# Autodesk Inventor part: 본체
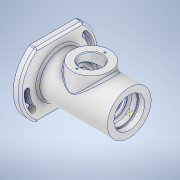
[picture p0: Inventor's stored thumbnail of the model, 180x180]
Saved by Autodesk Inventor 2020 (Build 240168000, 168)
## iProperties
Created: 2022-05
Part Number: 본체
Material: 알루미늄 6061
Document SubType Name: Modeling
Designer: Student
Density: 2.7 g/cm^3
Appearance: 알루미늄 - 평지
Mass: 703.309 g
Surface Area: 623.432 cm^2
Volume: 260.485 cm^3
Author: Student
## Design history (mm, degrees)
sketch "스케치1"
  geometry: L1 (65.838, 0)-(-65.838, 0); L2 (56, 32)-(-46, 32); L3 (-23.801, 32)-(-46, 32); L4 (-46, 32)-(-46, 58); L5 (-46, 58)-(-56, 58); L6 (-56, 58)-(-56, 36); L7 (-56, 36)-(-59, 36); L8 (-59, 36)-(-59, 30); L9 (-59, 30)-(-45, 20); L10 (-45, 20)-(-45, 15.19); L11 (-37.7, 14.786)-(-37.7, 11); L12 (-37.7, 11)-(-35, 11); L13 (-35, 11)-(-35, 15); L14 (-35, 15)-(-30, 15); L15 (-30, 15)-(-30, 17.5); L16 (-30, 17.5)-(-19, 17.5); L17 (-19, 17.5)-(-19, 27); L18 (-19, 27)-(19, 27); L19 (19, 27)-(19, 17.5); L20 (34, 17.5)-(34, 22.5); L21 (34, 22.5)-(45, 22.5); L22 (45, 22.5)-(45, 24); L23 (45, 24)-(48, 24); L24 (48, 24)-(48, 22.5); L25 (48, 22.5)-(56, 22.5); L26 (56, 22.5)-(56, 32); L27 (34, 17.5)-(30, 17.5); L28 (28.25, 17.5)-(28.25, 18.5); L29 (28.25, 18.5)-(30, 18.5); L30 (30, 18.5)-(30, 17.5); L31 (28.25, 17.5)-(19, 17.5); L32 (-44.3, 14.786)-(-45, 15.19); L33 (-44.3, 14.786)-(-37.7, 14.786); 2 further points
  constraints: 66 end point, 25 perpendicular, 3 horizontal, 1 coincident, 1 horizontal alignment, 1 midpoint, 1 point on line
  dimensions: "d2" = 102 distance between parallel lines of L4 L26; "d3" = 13 distance between parallel lines of L8 L4; "d4" = 3 distance of L6.end L7.end; "d5" = 64 diameter of L2 L1; "d6" = 48 diameter of L23 L1; "d7" = 45 diameter of L21 L1; "d8" = 54 diameter of L18 L1; "d9" = 30 diameter of L14 L1; "d10" = 22 diameter of L12 L1; "d11" = 40 diameter of L9.end L1; "d12" = 60 diameter of L8.end L1; "d13" = 72 diameter of L7 L1; "d14" = 8 distance of L24.end L25.end; "d15" = 3 distance of L22.end L23.end; "d16" = 22 distance between parallel lines of L20 L26; "d17" = 64 distance between parallel lines of L15 L20; "d18" = 11 distance of L27.end L19.end; "d19" = 38 distance of L17.end L18.end; "d20" = 11 distance between parallel lines of L15 L17; "d21" = 60 distance between parallel lines of L15 L30; "d22" = 5 distance between parallel lines of L13 L15; "d23" = 14 distance between parallel lines of L10 L8; "d24" = 116 diameter of L5 L1; "d26" = 37 diameter of L29 L1; "d28" = 1.75 distance of L28.end L29.end; "d29" = 7.3 distance between parallel lines of L10 L11; "d30" = 35 diameter of L31 L1; "d31" = 19 distance from line of point (0, 0) L19; "d32" = 45 diameter of L25 L1; "d33" = 0.7 distance from line of L32.start L10; "d34" = 30 deg angle of L33 L32
revolve "회전1" sketch "스케치1" stored, may be unused: angle "d35" = 90 deg
sketch "스케치2"
  geometry: L1 (-61.819, 47)-(63.766, 47); L2 (-61.819, -47)-(73.988, -47); C1 r 58 at (0, 0) reference; 5 further points
  constraints: 4 end point, 2 horizontal
  dimensions: "d36" = 47 distance from line of point (0, 0) L1; "d37" = 94 distance between parallel lines of L1 L2
extrude "돌출1" cut sketch "스케치2" distance "d38" = 10; taper "d39" = 0 deg
sketch "스케치5"
  geometry: L1 (0, 0)-(75.323, 0); L2 (0, 0)-(56.239, 47.19); C1 r 32 at (0, 0) reference; C2 r 20 at (0, 0) reference; A1 r 48 centre (0, 0) between (36.77, 30.854) and (-48, 0); A2 r 48 centre (0, 0) between (48, 0) and (36.77, 30.854); A3 r 52 centre (0, 0) between (52, 0) and (39.834, 33.425); A4 r 44 centre (0, 0) between (44, 0) and (33.706, 28.283); A5 r 4 centre (48, 0) between (44, 0) and (52, 0); A6 r 4 centre (36.77, 30.854) between (39.834, 33.425) and (33.706, 28.283); A7 r 48 centre (0, 0) between (-48, 0) and (-38.722, -28.366); A8 r 52 centre (0, 0) between (-52, 0) and (-41.949, -30.73); A9 r 44 centre (0, 0) between (-44, 0) and (-35.495, -26.002); A10 r 4 centre (-48, 0) between (-44, 0) and (-52, 0); A11 r 4 centre (-38.722, -28.366) between (-41.949, -30.73) and (-35.495, -26.002); 1 further point
  constraints: 22 point on circle, 11 centre point, 8 tangent, 4 end point, 3 coincident, 2 concentric, 1 horizontal, 1 point on line
  dimensions: "d51" = 96 diameter of A1; "d52" = 40 deg angle of L1 L2; "d53" = 8 diameter of A5; "d54" = 8 diameter of A11 (derived); "d55" = 48.41661 distance from line of L1.end L2; "d56" = 47.18977 distance from line of L2.end L1; "d57" = 0 distance from line of A3.start L1; "d58" = 26.00217 distance from line of A9.end L1; "d59" = 0 distance from line of A9.start L1
extrude "돌출3" cut sketch "스케치5" distance "d60" = 4.4; taper "d61" = 0 deg
sketch "스케치6"
  geometry: C1 r 4 at (-38.722, -28.366); C2 r 4 at (36.77, 30.854); A1 r 52 centre (0, 0) between (-52, 0) and (-41.949, -30.73) reference; A2 r 4 centre (-38.722, -28.366) between (-41.949, -30.73) and (-35.495, -26.002) reference; A3 r 44 centre (0, 0) between (-44, 0) and (-35.495, -26.002) reference; A4 r 4 centre (-48, 0) between (-44, 0) and (-52, 0) reference; A5 r 4 centre (48, 0) between (44, 0) and (52, 0) reference; A6 r 52 centre (0, 0) between (52, 0) and (39.834, 33.425) reference; A7 r 4 centre (36.77, 30.854) between (39.834, 33.425) and (33.706, 28.283) reference; A8 r 44 centre (0, 0) between (44, 0) and (33.706, 28.283) reference; A9 r 48 centre (0, 0) between (-48, 0) and (-38.722, -28.366); A10 r 50.25 centre (0, 0) between (-50.25, 0) and (-40.537, -29.696); A11 r 45.75 centre (0, 0) between (-45.75, 0) and (-36.907, -27.036); A12 r 2.25 centre (-48, 0) between (-45.75, 0) and (-50.25, 0); A13 r 2.25 centre (-38.722, -28.366) between (-40.537, -29.696) and (-36.907, -27.036); A14 r 48 centre (0, 0) between (48, 0) and (36.77, 30.854); A15 r 50.25 centre (0, 0) between (50.25, 0) and (38.494, 32.3); A16 r 45.75 centre (0, 0) between (45.75, 0) and (35.047, 29.408); A17 r 2.25 centre (48, 0) between (45.75, 0) and (50.25, 0); A18 r 2.25 centre (36.77, 30.854) between (38.494, 32.3) and (35.047, 29.408); 9 further points
  constraints: 20 point on circle, 12 centre point, 8 tangent, 4 coincident
  dimensions: "d62" = 4.5 diameter of A13; "d63" = 4.5 diameter of A17; "d64" = 8 diameter of C1; "d65" = 8 diameter of C2
extrude "돌출4" cut sketch "스케치6" extent not by distance; stored distance "d66" = 4.4; taper "d67" = 0 deg
node "작업 평면1"
sketch "스케치7"
  geometry: C1 r 27.5 at (0, 0); 1 further point
  constraints: 1 centre point, 1 coincident
  dimensions: "d69" = 55 diameter of C1
extrude "돌출5" join sketch "스케치7" stored distance "d70" = 10; taper "d71" = 5 deg
sketch "스케치8"
  geometry: C1 r 16 at (0, 0); 2 further points
  constraints: 1 centre point, 1 coincident, 1 vertical alignment
  dimensions: "d72" = 32 diameter of C1; "d73" = 20.5 distance of point (0, -20.5) point (0, 0)
extrude "돌출6" cut sketch "스케치8" stored distance "d74" = 10; taper "d75" = 0 deg
sketch "스케치9"
  geometry: 3 further points
  constraints: 2 vertical alignment
  dimensions: "d76" = 20.5 distance of point (0, 0) point (0, -20.5); "d84" = 20.5 distance of point (0, 20.5) point (0, 0)
hole "구멍1" sketch "스케치9" at (0, -20.5), (0, 20.5) diameter "d77" = 2.459; stored, may be unused: countersink angle "d81" = 90 deg, drill point angle "d83" = 118 deg; dims "d78" = 6, "d79" = 4, "d80" = 2, "d82" = 8.8
node "작업 평면2"
sketch "스케치10"
  geometry: L1 (-22.847, 8.471)-(34.847, 8.471); L2 (34.847, 8.471)-(34.847, -8.471); L3 (34.847, -8.471)-(-22.847, -8.471); L4 (-22.847, -8.471)-(-22.847, 8.471); L5 (-56, -47)-(-56, 47) reference; 3 further points
  constraints: 2 midpoint, 1 horizontal alignment, 1 parallel, 2 other
  dimensions: "d86" = 62 distance from line of L5 point (6, 8.471); "d87" = 90.84706 distance between parallel lines of L2 L5; "d88" = 16.94192 distance between parallel lines of L3 L1
feature "엠보싱1" sketch "스케치10" dims "d2" = 102, "d3" = 13, "d4" = 3, "d5" = 64, "d6" = 48, "d7" = 45, "d8" = 54, "d9" = 30, "d10" = 22, "d11" = 40, "d12" = 60, "d13" = 72, "d14" = 8, "d15" = 3, "d16" = 22, "d17" = 64, "d18" = 11, "d19" = 38, "d20" = 11, "d21" = 60, "d22" = 5, "d23" = 14, "d24" = 116, "d26" = 37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
fillet "모깎기1" dims "d91" = 3
fillet "모깎기2" dims "d92" = 0.6
fillet "모깎기4" dims "d94" = 0.5
fillet "모깎기5" dims "d95" = 3
chamfer "모따기1" distance "d96" = 1; stored, may be unused: second distance "d97" = 2, angle "d98" = 45 deg
sketch "스케치12"
  geometry: 1 further point
fillet "모깎기6" dims "d99" = 3
chamfer "모따기2" distance "d100" = 1; stored, may be unused: second distance "d101" = 2, angle "d102" = 45 deg
sketch "스케치15"
  geometry: 3 further points
  constraints: 2 coincident
node "솔리드1"
node "투영된 루프1"
node "투영된 루프2"
feature "A9D066F2-1C7D-4E18-AEED-F7BC21143FA4" dims "d77" = 2.459, "d78" = 6, "d79" = 4, "d80" = 2, "d81" = 90 deg, "d82" = 8.8, "d83" = 118 deg
other parameters: "d68" = 38, "d85" = -39.5
